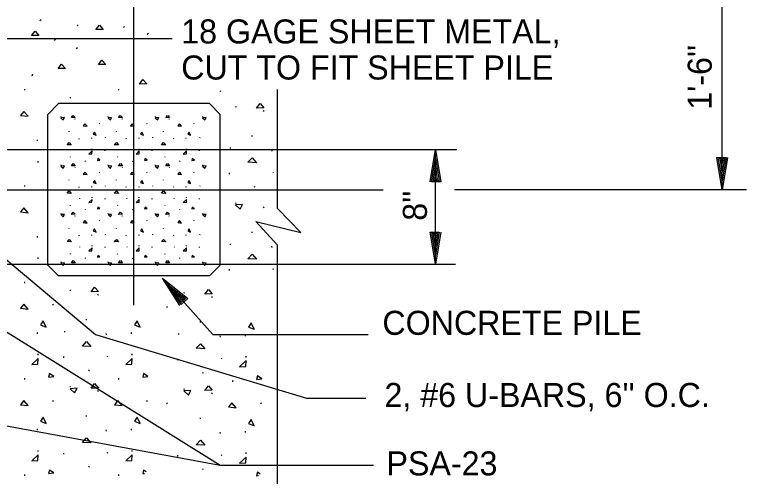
# Model space of a CAD drawing. Extents: x 22369.6 to 22428.3, y 22369.6 to 22415.
# Drawn here: x 22384.48 to 22390.13, y 22377.98 to 22381.54 of the extents above; entities that cross this region are included whole.
import ezdxf

# ---------------------------------------------------------------- set-up
doc = ezdxf.new("R2010")
doc.units = 0
for name, color, linetype in [('Level 1', 7, 'Continuous'), ('Level 2', 7, 'Continuous'), ('Level 4', 7, 'Continuous'), ('Level 8', 7, 'Continuous')]:
    doc.layers.add(name, color=color, linetype=linetype)

msp = doc.modelspace()

# ---------------------------------------------------------------- linework, layer by layer
at = {"layer": 'Level 1'}
for p, q in [((22385.4026, 22379.2979), (22385.4026, 22382.3467)), ((22389.9406, 22380.1886), (22389.9406, 22382.1836)), ((22384.3976, 22381.3555), (22385.6975, 22381.3555)), ((22386.5109, 22380.0441), (22386.5109, 22380.9629)), ((22386.4011, 22380.7933), (22386.406, 22380.8016)), ((22383.4494, 22380.4985), (22387.8926, 22380.4985)), ((22386.4692, 22380.4873), (22386.4664, 22380.4973)), ((22387.7279, 22379.614), (22387.7279, 22380.4985)), ((22387.7279, 22380.4985), (22387.7279, 22380.4985)), ((22387.7279, 22380.4295), (22387.7279, 22380.4295)), ((22383.6185, 22380.3207), (22385.1051, 22379.0706)), ((22389.9406, 22380.2578), (22389.9406, 22380.2578)), ((22384.403, 22380.1886), (22387.3254, 22380.1886)), ((22390.1265, 22380.1886), (22387.8757, 22380.1886)), ((22389.9406, 22380.1886), (22389.9406, 22380.1886)), ((22386.1893, 22380.082), (22386.1899, 22380.0893)), ((22386.6908, 22379.8584), (22386.5109, 22380.0441)), ((22386.5109, 22379.7606), (22386.3432, 22379.9439)), ((22386.3432, 22379.9439), (22386.6908, 22379.8584)), ((22386.5109, 22377.2675), (22386.5109, 22379.7606)), ((22387.7279, 22379.683), (22387.7279, 22379.683)), ((22383.4648, 22379.614), (22387.8841, 22379.614)), ((22387.7279, 22379.614), (22387.7279, 22379.614)), ((22386.0117, 22379.0706), (22385.6216, 22379.5072)), ((22385.6216, 22379.5072), (22385.6216, 22379.5072)), ((22383.9343, 22379.3935), (22386.0666, 22378.0617)), ((22385.1051, 22379.0706), (22386.7335, 22378.5805)), ((22386.0117, 22379.0706), (22387.2081, 22379.0706)), ((22384.6631, 22378.9114), (22384.6631, 22378.9207)), ((22386.7335, 22378.5805), (22387.1921, 22378.5805)), ((22384.1883, 22378.4081), (22386.0666, 22378.0617)), ((22384.6597, 22378.332), (22384.6597, 22378.3419)), ((22386.0666, 22378.0617), (22387.2504, 22378.0617))]:
    msp.add_line(p, q, dxfattribs=at)
msp.add_lwpolyline([(22385.1097, 22381.4254), (22385.1364, 22381.4608), (22385.1664, 22381.4268)], close=True, dxfattribs=at)
for points in [[(22387.6867, 22380.2504), (22387.7279, 22380.4985), (22387.769, 22380.2504), (22387.6987, 22380.2504), (22387.7279, 22380.4295), (22387.7557, 22380.261), (22387.7106, 22380.261), (22387.7279, 22380.3631), (22387.7424, 22380.2716), (22387.7239, 22380.2716), (22387.7279, 22380.2942)], [(22389.9818, 22380.4373), (22389.9406, 22380.1886), (22389.8994, 22380.4373), (22389.9698, 22380.4373), (22389.9406, 22380.2578), (22389.9127, 22380.4267), (22389.9579, 22380.4267), (22389.9406, 22380.3243), (22389.926, 22380.416), (22389.9446, 22380.416), (22389.9406, 22380.3934)], [(22387.769, 22379.8621), (22387.7279, 22379.614), (22387.6867, 22379.8621), (22387.7571, 22379.8621), (22387.7279, 22379.683), (22387.7, 22379.8515), (22387.7451, 22379.8515), (22387.7279, 22379.7493), (22387.7132, 22379.8409), (22387.7318, 22379.8409), (22387.7279, 22379.8183)], [(22385.7569, 22379.2937), (22385.6216, 22379.5072), (22385.8185, 22379.3488), (22385.7658, 22379.3017), (22385.6678, 22379.4555), (22385.8015, 22379.3479), (22385.7677, 22379.3177), (22385.7122, 22379.4058), (22385.7844, 22379.3469), (22385.7705, 22379.3345), (22385.7584, 22379.3541)]]:
    msp.add_lwpolyline(points, dxfattribs=at)
at = {"layer": 'Level 2'}
for p, q in [((22384.7376, 22380.7703), (22384.8209, 22380.8536)), ((22385.9842, 22380.8536), (22384.8209, 22380.8536)), ((22386.0676, 22380.7703), (22385.9842, 22380.8536)), ((22384.7376, 22379.6069), (22384.7376, 22380.7703)), ((22386.0676, 22379.6069), (22386.0676, 22380.7703)), ((22384.8209, 22379.5236), (22384.7376, 22379.6069)), ((22385.9842, 22379.5236), (22386.0676, 22379.6069)), ((22385.9842, 22379.5236), (22384.8209, 22379.5236))]:
    msp.add_line(p, q, dxfattribs=at)
at = {"layer": 'Level 8'}
for p, q in [((22384.5602, 22380.957), (22384.5617, 22380.9666)), ((22384.9119, 22380.8964), (22384.9126, 22380.9037)), ((22386.1893, 22380.8264), (22386.1899, 22380.8337)), ((22384.8399, 22380.7503), (22384.8402, 22380.754)), ((22384.9463, 22380.7337), (22384.9488, 22380.7378)), ((22385.2043, 22380.7503), (22385.2046, 22380.754)), ((22385.3107, 22380.7337), (22385.3132, 22380.7378)), ((22385.5687, 22380.7503), (22385.5691, 22380.754)), ((22385.6751, 22380.7337), (22385.6776, 22380.7378)), ((22385.9331, 22380.7503), (22385.9335, 22380.754)), ((22385.1391, 22380.6947), (22385.1368, 22380.6991)), ((22385.5035, 22380.6947), (22385.5012, 22380.6991)), ((22385.8679, 22380.6947), (22385.8656, 22380.6991)), ((22384.903, 22380.6366), (22384.9026, 22380.6407)), ((22385.2674, 22380.6366), (22385.2671, 22380.6407)), ((22385.6318, 22380.6366), (22385.6315, 22380.6407)), ((22386.3148, 22380.6001), (22386.3142, 22380.6082)), ((22384.6597, 22380.5653), (22384.6597, 22380.5752)), ((22384.9806, 22380.5799), (22384.9791, 22380.5849)), ((22385.0776, 22380.5839), (22385.0776, 22380.5889)), ((22385.1826, 22380.5898), (22385.1833, 22380.5936)), ((22385.345, 22380.5799), (22385.3436, 22380.5849)), ((22385.442, 22380.5839), (22385.442, 22380.5889)), ((22385.5471, 22380.5898), (22385.5477, 22380.5936)), ((22385.7094, 22380.5799), (22385.708, 22380.5849)), ((22385.8064, 22380.5839), (22385.8064, 22380.5889)), ((22385.9115, 22380.5898), (22385.9121, 22380.5936)), ((22384.9856, 22380.4937), (22384.9841, 22380.4973)), ((22385.0793, 22380.501), (22385.0793, 22380.5057)), ((22385.1796, 22380.4903), (22385.1796, 22380.4953)), ((22385.35, 22380.4937), (22385.3486, 22380.4973)), ((22385.4437, 22380.501), (22385.4437, 22380.5057)), ((22385.544, 22380.4903), (22385.544, 22380.4953)), ((22385.7144, 22380.4937), (22385.713, 22380.4973)), ((22385.8081, 22380.501), (22385.8081, 22380.5057)), ((22385.9084, 22380.4903), (22385.9084, 22380.4953)), ((22386.1462, 22380.5071), (22386.1475, 22380.5145)), ((22384.9119, 22380.4403), (22384.9137, 22380.4442)), ((22385.2763, 22380.4403), (22385.2781, 22380.4442)), ((22385.6407, 22380.4403), (22385.6426, 22380.4442)), ((22384.6631, 22380.4003), (22384.6631, 22380.4096)), ((22384.8399, 22380.3763), (22384.8402, 22380.3799)), ((22385.0276, 22380.4067), (22385.0283, 22380.4115)), ((22385.2043, 22380.3763), (22385.2046, 22380.3799)), ((22385.392, 22380.4067), (22385.3927, 22380.4115)), ((22385.5687, 22380.3763), (22385.5691, 22380.3799)), ((22385.7564, 22380.4067), (22385.7571, 22380.4115)), ((22385.9331, 22380.3763), (22385.9335, 22380.3799)), ((22384.9463, 22380.3596), (22384.9488, 22380.3638)), ((22385.1391, 22380.3206), (22385.1368, 22380.325)), ((22385.3107, 22380.3596), (22385.3132, 22380.3638)), ((22385.5035, 22380.3206), (22385.5012, 22380.325)), ((22385.6751, 22380.3596), (22385.6776, 22380.3638)), ((22385.8679, 22380.3206), (22385.8656, 22380.325)), ((22386.14, 22380.3089), (22386.14, 22380.3188)), ((22386.4792, 22380.3157), (22386.4763, 22380.3228)), ((22384.903, 22380.2625), (22384.9026, 22380.2666)), ((22385.2674, 22380.2625), (22385.2671, 22380.2666)), ((22385.6318, 22380.2625), (22385.6315, 22380.2666)), ((22384.5602, 22380.2126), (22384.5617, 22380.2222)), ((22384.9806, 22380.2058), (22384.9791, 22380.2108)), ((22385.0776, 22380.2098), (22385.0776, 22380.2148)), ((22385.1826, 22380.2158), (22385.1833, 22380.2195)), ((22385.345, 22380.2058), (22385.3436, 22380.2108)), ((22385.442, 22380.2098), (22385.442, 22380.2148)), ((22385.5471, 22380.2158), (22385.5477, 22380.2195)), ((22385.7094, 22380.2058), (22385.708, 22380.2108)), ((22385.8064, 22380.2098), (22385.8064, 22380.2148)), ((22385.9115, 22380.2158), (22385.9121, 22380.2195)), ((22386.3326, 22380.2094), (22386.3362, 22380.2172)), ((22384.9856, 22380.1196), (22384.9841, 22380.1232)), ((22385.0793, 22380.1269), (22385.0793, 22380.1316)), ((22385.1796, 22380.1162), (22385.1796, 22380.1212)), ((22385.35, 22380.1196), (22385.3486, 22380.1232)), ((22385.4437, 22380.1269), (22385.4437, 22380.1316)), ((22385.544, 22380.1162), (22385.544, 22380.1212)), ((22385.7144, 22380.1196), (22385.713, 22380.1232)), ((22385.8081, 22380.1269), (22385.8081, 22380.1316)), ((22385.9084, 22380.1162), (22385.9084, 22380.1212)), ((22384.9119, 22380.0662), (22384.9137, 22380.0701)), ((22385.0276, 22380.0326), (22385.0283, 22380.0374)), ((22385.2763, 22380.0662), (22385.2781, 22380.0701)), ((22385.392, 22380.0326), (22385.3927, 22380.0374)), ((22385.6407, 22380.0662), (22385.6426, 22380.0701)), ((22385.7564, 22380.0326), (22385.7571, 22380.0374)), ((22386.4011, 22380.0489), (22386.406, 22380.0571)), ((22384.8399, 22380.0022), (22384.8402, 22380.0058)), ((22384.9463, 22379.9855), (22384.9488, 22379.9897)), ((22385.2043, 22380.0022), (22385.2046, 22380.0058)), ((22385.3107, 22379.9855), (22385.3132, 22379.9897)), ((22385.5687, 22380.0022), (22385.5691, 22380.0058)), ((22385.6751, 22379.9855), (22385.6776, 22379.9897)), ((22385.9331, 22380.0022), (22385.9335, 22380.0058)), ((22385.1391, 22379.9465), (22385.1368, 22379.9509)), ((22385.5035, 22379.9465), (22385.5012, 22379.9509)), ((22385.8679, 22379.9465), (22385.8656, 22379.9509)), ((22384.903, 22379.8884), (22384.9026, 22379.8925)), ((22385.2674, 22379.8884), (22385.2671, 22379.8925)), ((22385.6318, 22379.8884), (22385.6315, 22379.8925)), ((22386.3148, 22379.8556), (22386.3142, 22379.8638)), ((22384.6597, 22379.8209), (22384.6597, 22379.8308)), ((22384.9806, 22379.8318), (22384.9791, 22379.8368)), ((22385.0776, 22379.8358), (22385.0776, 22379.8408)), ((22385.1826, 22379.8417), (22385.1833, 22379.8454)), ((22385.345, 22379.8318), (22385.3436, 22379.8368)), ((22385.442, 22379.8358), (22385.442, 22379.8408)), ((22385.5471, 22379.8417), (22385.5477, 22379.8454)), ((22385.7094, 22379.8318), (22385.708, 22379.8368)), ((22385.8064, 22379.8358), (22385.8064, 22379.8408)), ((22385.9115, 22379.8417), (22385.9121, 22379.8454)), ((22384.9856, 22379.7455), (22384.9841, 22379.7491)), ((22385.0793, 22379.7528), (22385.0793, 22379.7575)), ((22385.35, 22379.7455), (22385.3486, 22379.7491)), ((22385.4437, 22379.7528), (22385.4437, 22379.7575)), ((22385.7144, 22379.7455), (22385.713, 22379.7491)), ((22385.8081, 22379.7528), (22385.8081, 22379.7575)), ((22386.1462, 22379.7626), (22386.1475, 22379.7701)), ((22386.4692, 22379.7429), (22386.4664, 22379.7528)), ((22384.9119, 22379.6921), (22384.9137, 22379.696)), ((22385.1796, 22379.7421), (22385.1796, 22379.7471)), ((22385.2763, 22379.6921), (22385.2781, 22379.696)), ((22385.544, 22379.7421), (22385.544, 22379.7471)), ((22385.6407, 22379.6921), (22385.6426, 22379.696)), ((22385.9084, 22379.7421), (22385.9084, 22379.7471)), ((22384.6631, 22379.6558), (22384.6631, 22379.6651)), ((22385.0276, 22379.6585), (22385.0283, 22379.6633)), ((22385.392, 22379.6585), (22385.3927, 22379.6633)), ((22385.7564, 22379.6585), (22385.7571, 22379.6633)), ((22384.8399, 22379.6281), (22384.8402, 22379.6318)), ((22384.9463, 22379.6114), (22384.9488, 22379.6156)), ((22385.2043, 22379.6281), (22385.2046, 22379.6318)), ((22385.3107, 22379.6114), (22385.3132, 22379.6156)), ((22385.5687, 22379.6281), (22385.5691, 22379.6318)), ((22385.6751, 22379.6114), (22385.6776, 22379.6156)), ((22385.9331, 22379.6281), (22385.9335, 22379.6318)), ((22386.4792, 22379.5712), (22386.4763, 22379.5784)), ((22386.14, 22379.5645), (22386.14, 22379.5744)), ((22384.5602, 22379.4681), (22384.5617, 22379.4777)), ((22384.9119, 22379.4076), (22384.9126, 22379.4149)), ((22385.6678, 22379.4555), (22385.6678, 22379.4555)), ((22385.1237, 22379.3744), (22385.1286, 22379.3827)), ((22385.7907, 22379.3901), (22385.7913, 22379.3974)), ((22386.0024, 22379.3569), (22386.0074, 22379.3652)), ((22384.782, 22379.2968), (22384.7776, 22379.3056)), ((22385.6608, 22379.2793), (22385.6564, 22379.2881)), ((22385.0374, 22379.1812), (22385.0368, 22379.1894)), ((22385.9162, 22379.1637), (22385.9156, 22379.1719)), ((22384.6597, 22379.0764), (22384.6597, 22379.0864)), ((22384.8688, 22379.0882), (22384.8701, 22379.0957)), ((22385.1918, 22379.0685), (22385.189, 22379.0784)), ((22385.3849, 22379.0764), (22385.3849, 22379.0864)), ((22385.7476, 22379.0707), (22385.7489, 22379.0782)), ((22386.0706, 22379.051), (22386.0678, 22379.0609)), ((22386.2636, 22379.0589), (22386.2636, 22379.0689)), ((22385.2018, 22378.8968), (22385.1989, 22378.904)), ((22385.3883, 22378.9114), (22385.3883, 22378.9207)), ((22386.2671, 22378.8939), (22386.2671, 22378.9032)), ((22384.8626, 22378.89), (22384.8626, 22378.9)), ((22385.7414, 22378.8725), (22385.7414, 22378.8825)), ((22386.0806, 22378.8793), (22386.0777, 22378.8865)), ((22385.0552, 22378.7905), (22385.0588, 22378.7983)), ((22384.5602, 22378.7237), (22384.5617, 22378.7333)), ((22385.2854, 22378.7237), (22385.2868, 22378.7333)), ((22385.9339, 22378.773), (22385.9376, 22378.7808)), ((22386.1641, 22378.7062), (22386.1656, 22378.7158)), ((22384.9119, 22378.6632), (22384.9126, 22378.6705)), ((22385.1237, 22378.63), (22385.1286, 22378.6383)), ((22385.7907, 22378.6457), (22385.7913, 22378.653)), ((22386.0024, 22378.6125), (22386.0074, 22378.6208)), ((22384.782, 22378.5524), (22384.7776, 22378.5612)), ((22385.5072, 22378.5524), (22385.5027, 22378.5612)), ((22385.6608, 22378.5349), (22385.6564, 22378.5437)), ((22386.386, 22378.5349), (22386.3815, 22378.5437)), ((22385.0374, 22378.4368), (22385.0368, 22378.4449)), ((22385.9162, 22378.4193), (22385.9156, 22378.4274)), ((22385.3849, 22378.332), (22385.3849, 22378.3419)), ((22385.1918, 22378.324), (22385.189, 22378.334)), ((22386.0706, 22378.3065), (22386.0678, 22378.3165)), ((22386.2636, 22378.3145), (22386.2636, 22378.3244)), ((22384.6631, 22378.167), (22384.6631, 22378.1763)), ((22385.3883, 22378.167), (22385.3883, 22378.1763)), ((22384.8626, 22378.1456), (22384.8626, 22378.1555)), ((22385.2018, 22378.1524), (22385.1989, 22378.1595)), ((22385.7414, 22378.1281), (22385.7414, 22378.138)), ((22386.0806, 22378.1349), (22386.0777, 22378.142)), ((22386.2671, 22378.1495), (22386.2671, 22378.1588)), ((22385.0552, 22378.0461), (22385.0588, 22378.0539)), ((22385.9339, 22378.0286), (22385.9376, 22378.0364)), ((22384.5602, 22377.9793), (22384.5617, 22377.9889)), ((22385.2854, 22377.9793), (22385.2868, 22377.9889))]:
    msp.add_line(p, q, dxfattribs=at)
for points in [[(22384.6864, 22381.5024), (22384.6777, 22381.494)], [(22384.9729, 22381.4628), (22384.9642, 22381.4544)], [(22385.3294, 22381.4496), (22385.3208, 22381.4412)], [(22385.5141, 22381.3969), (22385.5055, 22381.3884)], [(22384.7946, 22381.3507), (22384.786, 22381.3423)], [(22384.9665, 22381.2848), (22384.9579, 22381.2763)], [(22384.6227, 22381.0803), (22384.6141, 22381.0719)], [(22384.6141, 22381.0719), (22384.6224, 22381.0726)], [(22385.2854, 22380.957), (22385.2865, 22380.9644)], [(22386.0712, 22380.9482), (22386.0723, 22380.9557)], [(22384.9201, 22380.7468), (22384.9324, 22380.7631)], [(22384.9486, 22380.7475), (22384.9201, 22380.7468)], [(22384.9349, 22380.7631), (22384.9486, 22380.7475)], [(22385.2846, 22380.7468), (22385.2968, 22380.7631)], [(22385.3131, 22380.7475), (22385.2846, 22380.7468)], [(22385.2993, 22380.7631), (22385.3131, 22380.7475)], [(22385.649, 22380.7468), (22385.6612, 22380.7631)], [(22385.6775, 22380.7475), (22385.649, 22380.7468)], [(22385.6637, 22380.7631), (22385.6775, 22380.7475)], [(22385.4764, 22378.0245), (22385.4699, 22377.9967)], [(22385.4699, 22377.9967), (22385.4846, 22377.9986)], [(22385.4973, 22378.0105), (22385.4764, 22378.0245)], [(22386.3552, 22378.007), (22386.3487, 22377.9792)], [(22386.3761, 22377.993), (22386.3552, 22378.007)], [(22386.3487, 22377.9792), (22386.3634, 22377.9811)]]:
    msp.add_lwpolyline(points, dxfattribs=at)
for points in [[(22384.613, 22381.3793), (22384.6397, 22381.4146), (22384.6697, 22381.3806)], [(22384.8176, 22381.1243), (22384.8443, 22381.1596), (22384.8743, 22381.1256)], [(22385.1293, 22381.1551), (22385.156, 22381.1904), (22385.186, 22381.1564)], [(22385.4449, 22381.005), (22385.4716, 22381.0403), (22385.5016, 22381.0063)], [(22386.349, 22380.8195), (22386.3757, 22380.8548), (22386.4057, 22380.8208)], [(22384.5865, 22380.7558), (22384.5537, 22380.7936), (22384.5273, 22380.7623)], [(22384.8386, 22380.7449), (22384.8564, 22380.7291), (22384.8659, 22380.7468)], [(22385.2031, 22380.7449), (22385.2208, 22380.7291), (22385.2303, 22380.7468)], [(22385.5675, 22380.7449), (22385.5852, 22380.7291), (22385.5947, 22380.7468)], [(22385.9319, 22380.7449), (22385.9496, 22380.7291), (22385.9591, 22380.7468)], [(22385.0408, 22380.6797), (22385.0243, 22380.6987), (22385.0111, 22380.6829)], [(22385.4052, 22380.6797), (22385.3887, 22380.6987), (22385.3755, 22380.6829)], [(22385.7696, 22380.6797), (22385.7531, 22380.6987), (22385.7399, 22380.6829)], [(22385.0884, 22380.6189), (22385.1111, 22380.6101), (22385.0991, 22380.6347)], [(22385.4528, 22380.6189), (22385.4756, 22380.6101), (22385.4636, 22380.6347)], [(22385.8172, 22380.6189), (22385.84, 22380.6101), (22385.828, 22380.6347)], [(22384.8866, 22380.5365), (22384.9025, 22380.5537), (22384.9195, 22380.5347)], [(22385.2511, 22380.5365), (22385.2669, 22380.5537), (22385.2839, 22380.5347)], [(22385.6155, 22380.5365), (22385.6313, 22380.5537), (22385.6483, 22380.5347)], [(22385.0781, 22380.4663), (22385.0793, 22380.4885), (22385.0546, 22380.4644)], [(22385.4425, 22380.4663), (22385.4437, 22380.4885), (22385.4191, 22380.4644)], [(22385.8069, 22380.4663), (22385.8081, 22380.4885), (22385.7835, 22380.4644)], [(22385.1203, 22380.4154), (22385.1406, 22380.418), (22385.1236, 22380.4294)], [(22385.4847, 22380.4154), (22385.505, 22380.418), (22385.488, 22380.4294)], [(22385.8491, 22380.4154), (22385.8694, 22380.418), (22385.8524, 22380.4294)], [(22386.2823, 22380.4009), (22386.3138, 22380.4351), (22386.3477, 22380.3973)], [(22384.8386, 22380.3708), (22384.8564, 22380.355), (22384.8659, 22380.3728)], [(22384.9201, 22380.3728), (22384.9336, 22380.3905), (22384.9486, 22380.3734)], [(22385.2031, 22380.3708), (22385.2208, 22380.355), (22385.2303, 22380.3728)], [(22385.2846, 22380.3728), (22385.298, 22380.3905), (22385.3131, 22380.3734)], [(22385.5675, 22380.3708), (22385.5852, 22380.355), (22385.5947, 22380.3728)], [(22385.649, 22380.3728), (22385.6624, 22380.3905), (22385.6775, 22380.3734)], [(22385.9319, 22380.3708), (22385.9496, 22380.355), (22385.9591, 22380.3728)], [(22385.0408, 22380.3056), (22385.0243, 22380.3246), (22385.0111, 22380.3088)], [(22385.4052, 22380.3056), (22385.3887, 22380.3246), (22385.3755, 22380.3088)], [(22385.7696, 22380.3056), (22385.7531, 22380.3246), (22385.7399, 22380.3088)], [(22385.0884, 22380.2448), (22385.1111, 22380.236), (22385.0991, 22380.2606)], [(22385.4528, 22380.2448), (22385.4756, 22380.236), (22385.4636, 22380.2606)], [(22385.8172, 22380.2448), (22385.84, 22380.236), (22385.828, 22380.2606)], [(22384.8866, 22380.1624), (22384.9025, 22380.1796), (22384.9195, 22380.1606)], [(22385.2511, 22380.1624), (22385.2669, 22380.1796), (22385.2839, 22380.1606)], [(22385.6155, 22380.1624), (22385.6313, 22380.1796), (22385.6483, 22380.1606)], [(22385.0781, 22380.0922), (22385.0793, 22380.1144), (22385.0546, 22380.0903)], [(22385.4425, 22380.0922), (22385.4437, 22380.1144), (22385.4191, 22380.0903)], [(22385.8069, 22380.0922), (22385.8081, 22380.1144), (22385.7835, 22380.0903)], [(22384.5865, 22380.0114), (22384.5537, 22380.0492), (22384.5273, 22380.0179)], [(22385.1203, 22380.0413), (22385.1406, 22380.0439), (22385.1236, 22380.0553)], [(22385.4847, 22380.0413), (22385.505, 22380.0439), (22385.488, 22380.0553)], [(22385.8491, 22380.0413), (22385.8694, 22380.0439), (22385.8524, 22380.0553)], [(22386.1868, 22380.0712), (22386.2221, 22380.0397), (22386.241, 22380.0751)], [(22384.8386, 22379.9968), (22384.8564, 22379.9809), (22384.8659, 22379.9987)], [(22384.9201, 22379.9987), (22384.9336, 22380.0164), (22384.9486, 22379.9993)], [(22385.2031, 22379.9968), (22385.2208, 22379.9809), (22385.2303, 22379.9987)], [(22385.2846, 22379.9987), (22385.298, 22380.0164), (22385.3131, 22379.9993)], [(22385.5675, 22379.9968), (22385.5852, 22379.9809), (22385.5947, 22379.9987)], [(22385.649, 22379.9987), (22385.6624, 22380.0164), (22385.6775, 22379.9993)], [(22385.9319, 22379.9968), (22385.9496, 22379.9809), (22385.9591, 22379.9987)], [(22385.0408, 22379.9315), (22385.0243, 22379.9505), (22385.0111, 22379.9348)], [(22385.4052, 22379.9315), (22385.3887, 22379.9505), (22385.3755, 22379.9348)], [(22385.7696, 22379.9315), (22385.7531, 22379.9505), (22385.7399, 22379.9348)], [(22385.0884, 22379.8708), (22385.1111, 22379.8619), (22385.0991, 22379.8865)], [(22385.4528, 22379.8708), (22385.4756, 22379.8619), (22385.4636, 22379.8865)], [(22385.8172, 22379.8708), (22385.84, 22379.8619), (22385.828, 22379.8865)], [(22384.8866, 22379.7883), (22384.9025, 22379.8055), (22384.9195, 22379.7865)], [(22385.2511, 22379.7883), (22385.2669, 22379.8055), (22385.2839, 22379.7865)], [(22385.6155, 22379.7883), (22385.6313, 22379.8055), (22385.6483, 22379.7865)], [(22385.0781, 22379.7181), (22385.0793, 22379.7403), (22385.0546, 22379.7163)], [(22385.4425, 22379.7181), (22385.4437, 22379.7403), (22385.4191, 22379.7163)], [(22385.8069, 22379.7181), (22385.8081, 22379.7403), (22385.7835, 22379.7163)], [(22384.9201, 22379.6246), (22384.9336, 22379.6423), (22384.9486, 22379.6253)], [(22385.1203, 22379.6673), (22385.1406, 22379.6698), (22385.1236, 22379.6813)], [(22385.2846, 22379.6246), (22385.298, 22379.6423), (22385.3131, 22379.6253)], [(22385.4847, 22379.6673), (22385.505, 22379.6698), (22385.488, 22379.6813)], [(22385.649, 22379.6246), (22385.6624, 22379.6423), (22385.6775, 22379.6253)], [(22385.8491, 22379.6673), (22385.8694, 22379.6698), (22385.8524, 22379.6813)], [(22386.2823, 22379.6565), (22386.3138, 22379.6906), (22386.3477, 22379.6528)], [(22384.8386, 22379.6227), (22384.8564, 22379.6068), (22384.8659, 22379.6246)], [(22385.2031, 22379.6227), (22385.2208, 22379.6068), (22385.2303, 22379.6246)], [(22385.5675, 22379.6227), (22385.5852, 22379.6068), (22385.5947, 22379.6246)], [(22385.9319, 22379.6227), (22385.9496, 22379.6068), (22385.9591, 22379.6246)], [(22385.0716, 22379.4006), (22385.0983, 22379.4359), (22385.1283, 22379.402)], [(22385.9504, 22379.3831), (22385.9771, 22379.4184), (22386.0071, 22379.3845)], [(22384.5865, 22379.267), (22384.5537, 22379.3048), (22384.5273, 22379.2734)], [(22384.6812, 22379.1461), (22384.7265, 22379.1285), (22384.7026, 22379.1774)], [(22385.4064, 22379.1461), (22385.4517, 22379.1285), (22385.4278, 22379.1774)], [(22386.2852, 22379.1286), (22386.3305, 22379.111), (22386.3066, 22379.1599)], [(22385.0049, 22378.9821), (22385.0364, 22379.0162), (22385.0703, 22378.9784)], [(22385.8837, 22378.9646), (22385.9152, 22378.9987), (22385.9491, 22378.9609)], [(22384.6607, 22378.8423), (22384.6631, 22378.8865), (22384.6141, 22378.8386)], [(22385.3858, 22378.8423), (22385.3883, 22378.8865), (22385.3392, 22378.8386)], [(22386.2646, 22378.8248), (22386.2671, 22378.869), (22386.218, 22378.8211)], [(22384.7447, 22378.7411), (22384.785, 22378.7462), (22384.7512, 22378.769)], [(22385.4699, 22378.7411), (22385.5102, 22378.7462), (22385.4764, 22378.769)], [(22386.3487, 22378.7236), (22386.389, 22378.7287), (22386.3552, 22378.7515)], [(22385.0716, 22378.6562), (22385.0983, 22378.6915), (22385.1283, 22378.6575)], [(22384.9094, 22378.6524), (22384.9447, 22378.6209), (22384.9636, 22378.6562)], [(22385.7882, 22378.6349), (22385.8235, 22378.6034), (22385.8424, 22378.6387)], [(22385.9504, 22378.6387), (22385.9771, 22378.674), (22386.0071, 22378.64)], [(22384.5865, 22378.5225), (22384.5537, 22378.5603), (22384.5273, 22378.529)], [(22385.3117, 22378.5225), (22385.2789, 22378.5603), (22385.2525, 22378.529)], [(22386.1905, 22378.505), (22386.1577, 22378.5429), (22386.1313, 22378.5115)], [(22384.6812, 22378.4016), (22384.7265, 22378.3841), (22384.7026, 22378.433)], [(22385.4064, 22378.4016), (22385.4517, 22378.3841), (22385.4278, 22378.433)], [(22386.2852, 22378.3841), (22386.3305, 22378.3666), (22386.3066, 22378.4155)], [(22385.0049, 22378.2376), (22385.0364, 22378.2718), (22385.0703, 22378.234)], [(22385.8837, 22378.2201), (22385.9152, 22378.2543), (22385.9491, 22378.2165)], [(22384.6607, 22378.0978), (22384.6631, 22378.1421), (22384.6141, 22378.0942)], [(22385.3858, 22378.0978), (22385.3883, 22378.1421), (22385.3392, 22378.0942)], [(22386.2646, 22378.0803), (22386.2671, 22378.1246), (22386.218, 22378.0767)], [(22384.7447, 22377.9967), (22384.785, 22378.0018), (22384.7512, 22378.0245)]]:
    msp.add_lwpolyline(points, close=True, dxfattribs=at)

# ---------------------------------------------------------------- texts
at = {"layer": 'Level 4'}
for s, height, p in [('18 GAGE SHEET METAL,', 0.185698, (22385.7672, 22381.3184)), ('CUT TO FIT SHEET PILE', 0.185698, (22385.7672, 22381.0399)), ('CONCRETE PILE', 0.185698, (22387.3188, 22379.0682)), ("2, #6 U-BARS, 6'' O.C.", 0.185698, (22387.3349, 22378.511)), ('PSA-23', 0.1857, (22387.3506, 22377.9828))]:
    msp.add_text(s, height=height, dxfattribs=at).set_placement(p)
for s, p in [("1'-6''", (22389.8595, 22380.807)), ("8''", (22387.6623, 22379.9494))]:
    msp.add_text(s, height=0.1857, rotation=90, dxfattribs=at).set_placement(p)

doc.saveas('drawing.dxf')
